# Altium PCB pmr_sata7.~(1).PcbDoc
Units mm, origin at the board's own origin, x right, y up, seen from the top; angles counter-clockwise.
Board outline 160 x 99.92 mm, 2 copper layers (Top Layer, Bottom Layer); 11 components, 38 nets, 173 pads, 16 vias.
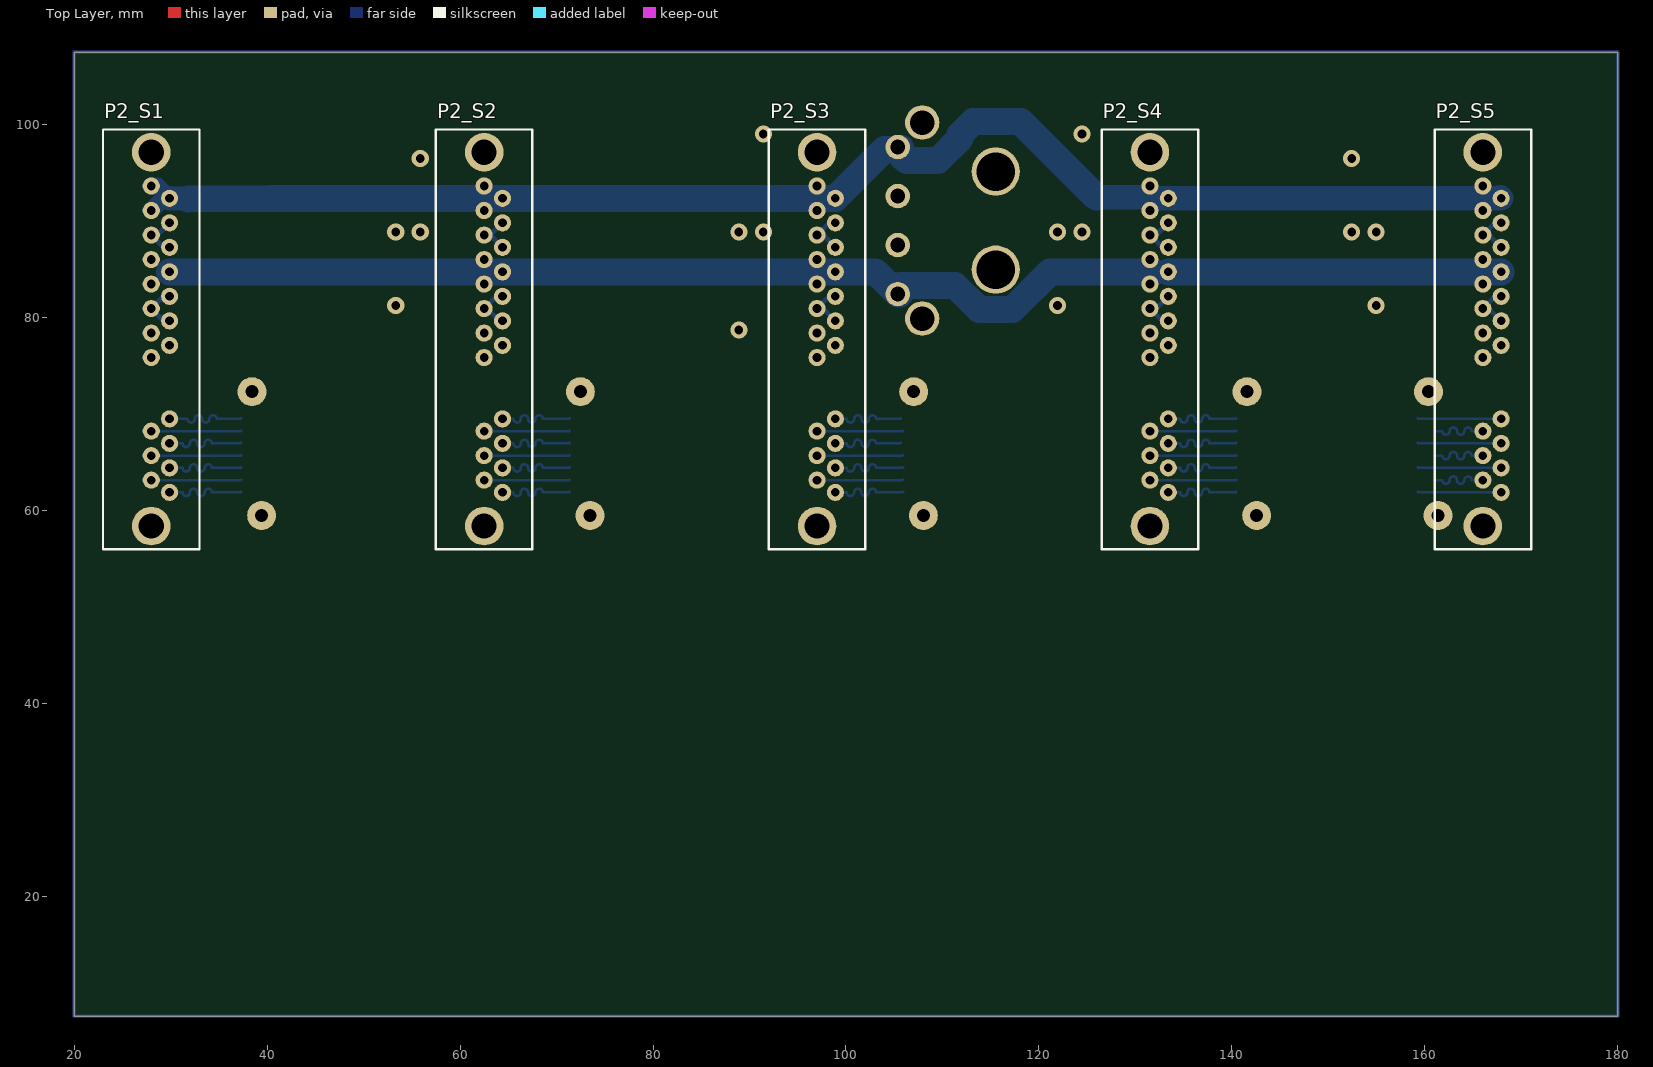
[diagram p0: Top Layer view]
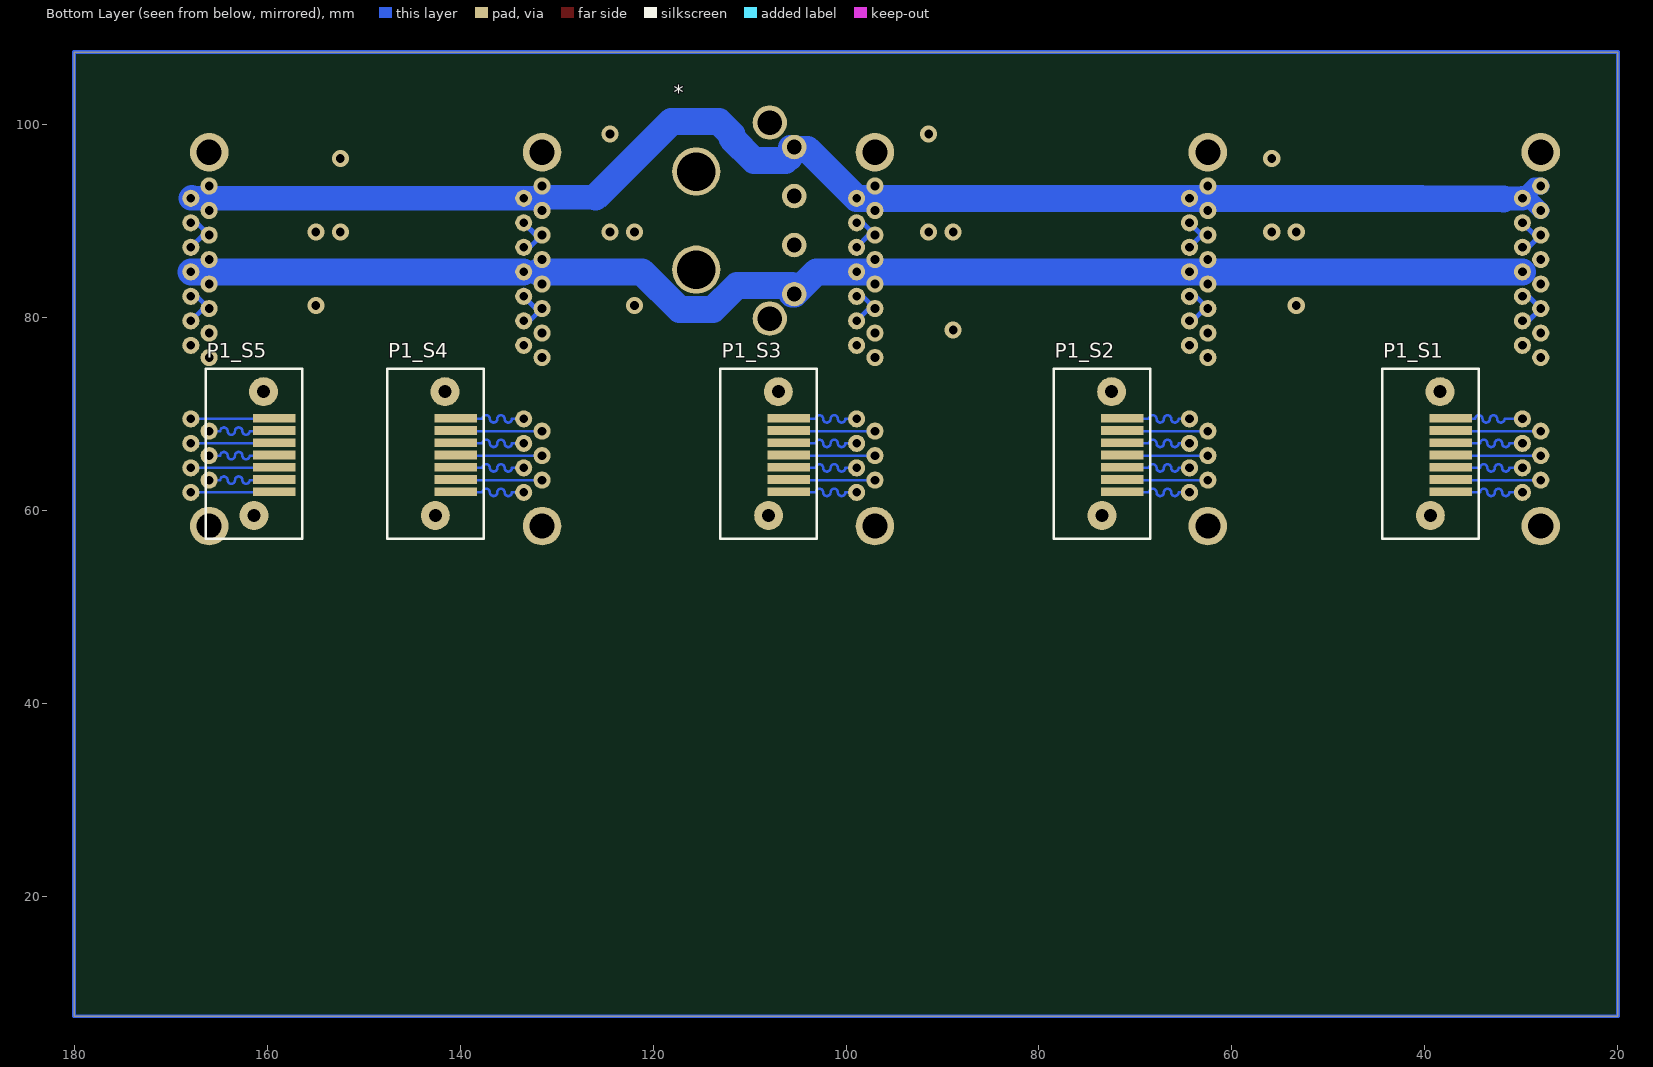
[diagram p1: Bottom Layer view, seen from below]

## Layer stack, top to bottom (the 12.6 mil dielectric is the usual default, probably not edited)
Top Solder: solder mask 0.0102, Solder Resist, Dk 3.5
Top Layer: signal copper 0.0356
Dielectric1: dielectric 0.32, FR-4, Dk 4.8
Bottom Layer: signal copper 0.0356
Bottom Solder: solder mask 0.0102, Solder Resist, Dk 3.5

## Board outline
20,7.62 20,107.544 180,107.544 180,7.62

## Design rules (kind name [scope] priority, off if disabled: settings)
Clearance [All] p1: gap=0.254
DiffPairsRouting [All] p1: maxlimit=0.254 minlimit=0.254 mostfreqgap=0.254 toplayer_minwidth=0.254 toplayer_maxwidth=0.381 toplayer_prefwidth=0.381 bottomlayer_minwidth=0.254 bottomlayer_maxwidth=0.381 bottomlayer_prefwidth=0.381 maxuncoupledlength=12.7
PolygonConnect [All] p1: connectstyle=Relief reliefconductorwidth=0.254 reliefentries=4 polygonreliefangle="90 Angle" airgapwidth=0.254
RoomDefinition top_level_sheet [InComponentClass('top_level_sheet')] p1 off: confinementstyle=ConfineIn formatcopy=TRUE lockcomponents=FALSE outline 180,10 197.5,10 197.5,37.5 180,37.5
RoomDefinition S5 [InComponentClass('S5')] p2 off: confinementstyle=ConfineIn formatcopy=TRUE lockcomponents=FALSE outline 29,122 53,122 53,170 29,170
RoomDefinition S3 [InComponentClass('S3')] p3 off: confinementstyle=ConfineIn formatcopy=TRUE lockcomponents=FALSE outline 76,114.83 100,114.83 100,162.83 76,162.83
RoomDefinition S2 [InComponentClass('S2')] p4 off: confinementstyle=ConfineIn formatcopy=TRUE lockcomponents=FALSE outline 108,115 132,115 132,163 108,163
RoomDefinition S1 [InComponentClass('S1')] p5 off: confinementstyle=ConfineIn formatcopy=TRUE lockcomponents=FALSE outline 127,116 151,116 151,164 127,164
RoomDefinition S4 [InComponentClass('S4')] p6 off: confinementstyle=ConfineIn formatcopy=TRUE lockcomponents=FALSE outline 192.278,29.464 184.912,29.464 184.912,40.386 192.278,40.386
RoutingVias [All] p1: holewidth=0.711 width=1.27 viastyle="Through Hole" minholewidth=0.711 minwidth=1.27 maxholewidth=0.711 maxwidth=1.27
SilkToSolderMaskClearance SilkscreenOverComponentPads [IsPad] p1: minsilkscreentomaskgap=0.254 clearancetoexposedcopper=TRUE
SolderMaskExpansion [All] p1: expansion=0.102
Width [All] p1: maxlimit=12.7 minlimit=0.254 preferedwidth=0.254
28 further rules are at their usual default settings.

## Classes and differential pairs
component class S1: P1_S1 P2_S1
component class S2: P1_S2 P2_S2
component class S3: P1_S3 P2_S3
component class S4: P1_S4 P2_S4
component class S5: P1_S5 P2_S5
channel class pmr_sata_single: S1 S2 S3 S4 S5
differential pair PAIR1_S1: +PAIR1_S1_P -PAIR1_S1_N
differential pair PAIR1_S2: +PAIR1_S2_P -PAIR1_S2_N
differential pair PAIR1_S3: +PAIR1_S3_P -PAIR1_S3_N
differential pair PAIR1_S4: +PAIR1_S4_P -PAIR1_S4_N
differential pair PAIR1_S5: +PAIR1_S5_P -PAIR1_S5_N
differential pair PAIR2_S1: +PAIR2_S1_P -PAIR2_S1_N
differential pair PAIR2_S2: +PAIR2_S2_P -PAIR2_S2_N
differential pair PAIR2_S3: +PAIR2_S3_P -PAIR2_S3_N
differential pair PAIR2_S4: +PAIR2_S4_P -PAIR2_S4_N
differential pair PAIR2_S5: +PAIR2_S5_P -PAIR2_S5_N

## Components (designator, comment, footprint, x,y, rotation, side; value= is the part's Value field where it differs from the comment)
* "PC_PWR_MOLEX" PC_PWR_MOLEX 115.52,90.08 r90 bottom
P1_S1 "SATA lille" "PMR_SATA -LILLE NY" 39.438,59.516 r270 bottom (schematic designator P1)
P1_S2 "SATA lille" "PMR_SATA -LILLE NY" 73.474,59.516 r270 bottom (schematic designator P1)
P1_S3 "SATA lille" "PMR_SATA -LILLE NY" 108.018,59.516 r270 bottom (schematic designator P1)
P1_S4 "SATA lille" "PMR_SATA -LILLE NY" 142.562,59.516 r270 bottom (schematic designator P1)
P1_S5 "SATA lille" "PMR_SATA -LILLE NY" 161.358,59.516 r270 bottom (schematic designator P1)
P2_S1 "SATA STOR" pmr_sata 28,58.42 r90 top (schematic designator P2)
P2_S2 "SATA STOR" pmr_sata 62.5,58.42 r90 top (schematic designator P2)
P2_S3 "SATA STOR" pmr_sata 97,58.42 r90 top (schematic designator P2)
P2_S4 "SATA STOR" pmr_sata 131.5,58.42 r90 top (schematic designator P2)
P2_S5 "SATA STOR" pmr_sata 166,58.42 r90 top (schematic designator P2)

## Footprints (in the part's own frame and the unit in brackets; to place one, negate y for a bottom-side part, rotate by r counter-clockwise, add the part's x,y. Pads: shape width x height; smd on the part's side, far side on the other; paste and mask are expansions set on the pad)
PC_PWR_MOLEX [mil]
  round 100 hole 60: 1(300,-400) 2(100,-400) 3(-100,-400) 4(-300,-400)
  round 140 hole 100: 5(400,-300) 6(-400,-300)
  round 196.85 hole 157.48: 7(-200,0) 8(200,0)
pmr_sata [mm]
  round 1.778 hole 0.9: P1(17.46,0) P2(18.73,-1.9) P3(20,0) P4(21.27,-1.9) P5(22.54,0) P6(23.81,-1.9) P7(25.08,0) P8(26.35,-1.9) P9(27.62,0) P10(28.89,-1.9) P11(30.16,0) P12(31.43,-1.9) P13(32.7,0) P14(33.97,-1.9) P15(35.24,0) S1(3.49,-1.9) S2(4.76,0) S3(6.03,-1.9) S4(7.3,0) S5(8.57,-1.9) S6(9.84,0) S7(11.11,-1.9)
  round 4 hole 2.6: S8(0,0) S8(38.74,0)
  silkscreen extent -2.4,-5 41.1,5
"PMR_SATA -LILLE NY" [mm]
  rect 0.9x4.4 smd: S1(-2.46,2.1) S2(-3.73,2.1) S3(-5,2.1) S4(-6.27,2.1) S5(-7.54,2.1) S6(-8.81,2.1) S7(-10.08,2.1)
  round 3 hole 1.35: S8(-12.83,1) S8(0,0)
  silkscreen extent -15.2,-5 2.4,5

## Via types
v1: diameter 1.778, hole 0.9, Top Layer to Bottom Layer, 16 vias

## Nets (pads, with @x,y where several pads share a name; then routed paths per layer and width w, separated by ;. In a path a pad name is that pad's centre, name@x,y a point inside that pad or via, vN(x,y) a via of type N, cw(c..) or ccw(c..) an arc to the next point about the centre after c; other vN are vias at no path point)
5V: *.4 P2_S1.P7 P2_S1.P8 P2_S1.P9 P2_S2.P7 P2_S2.P8 P2_S2.P9 P2_S3.P7 P2_S3.P8 P2_S3.P9 P2_S4.P7 P2_S4.P8 P2_S4.P9 P2_S5.P7 P2_S5.P8 P2_S5.P9 | length 141
  Bottom Layer w2.794: P2_S1.P8 P2_S2.P8 P2_S3.P8 103.05,84.77 *.4 105.591,82.46 105.591,83.349 111.301,83.349 113.801,80.849 117.239,80.849 121.16,84.77 131.92,84.77 ; P2_S4.P8 P2_S5.P8
12V: *.1 P2_S1.P13 P2_S1.P14 P2_S1.P15 P2_S2.P13 P2_S2.P14 P2_S2.P15 P2_S3.P13 P2_S3.P14 P2_S3.P15 P2_S4.P13 P2_S4.P14 P2_S4.P15 P2_S5.P13 P2_S5.P14 P2_S5.P15 | length 150.8
  Bottom Layer w1.778: P2_S1.P13 P2_S1.P14@29.27,92.39 ; P2_S1.P15 28.63,93.66 P2_S1.P14
  Bottom Layer w2.54: P2_S1.P14 31.877,92.329 ; *.1@105.116,97.456 *.1 105.77,97.7 *.1@105.77,96.52 ; 125.94,92.5 131.92,92.5 132.03,92.39 P2_S4.P14 P2_S5.P14 P2_S5.P14@167.79,92.5
  Bottom Layer w2.794: 31.877,92.329 40.386,92.373 56.896,92.373 56.913,92.39 P2_S2.P14 65.452,92.39 65.469,92.373 80.01,92.373 80.027,92.39 P2_S3.P14 103.966,97.456 *.1@105.116,97.456 ; 106.052,96.52 106.269,96.303 109.531,96.303 111.837,98.609 111.837,99.01 113.157,100.33 118.11,100.33 125.94,92.5
GND: P2_S1.P4 P2_S1.P5 P2_S1.P6 P2_S1.P10 P2_S1.P11 P2_S1.P12 P2_S2.P4 P2_S2.P5 P2_S2.P6 P2_S2.P10 P2_S2.P11 P2_S2.P12 P2_S3.P4 P2_S3.P5 P2_S3.P6 P2_S3.P10 P2_S3.P11 P2_S3.P12 P2_S4.P4 P2_S4.P5 P2_S4.P6 P2_S4.P10 P2_S4.P11 P2_S4.P12 P2_S5.P4 P2_S5.P5 P2_S5.P6 P2_S5.P10 P2_S5.P11 P2_S5.P12 | length 49.2
  Bottom Layer w0.508: P2_S1.P4 29.27,79.69 P2_S1.P5 29.27,82.23 P2_S1.P6 ; P2_S1.P10 29.27,87.31 P2_S1.P11 28.63,88.58 P2_S1.P12 ; P2_S2.P11 P2_S2.P11@63.13,88.58 ; P2_S2.P4 64.074,79.69 62.804,80.96 P2_S2.P5 63.77,82.23 P2_S2.P6 ; P2_S2.P10@64.4,86.675 P2_S2.P10 P2_S2.P11@63.13,88.58 ; P2_S2.P12 P2_S2.P11@63.13,88.58 ; P2_S3.P4 97.63,80.96 P2_S3.P5 98.27,82.23 P2_S3.P6 ; P2_S3.P10 97.63,88.58 P2_S3.P11 98.27,89.85 P2_S3.P12 ; P2_S4.P4 132.77,79.69 P2_S4.P5 132.13,80.96 P2_S4.P6 P2_S4.P6@133.4,82.865 ; P2_S4.P10 132.77,87.31 P2_S4.P11 132.13,88.58 P2_S4.P12 ; P2_S5.P4 166.63,80.96 P2_S5.P5 167.27,82.23 P2_S5.P6 ; P2_S5.P10 166.63,88.58 P2_S5.P11 167.27,89.85 P2_S5.P12
  other v1: 88.9,78.74 53.34,81.28 121.92,81.28 154.94,81.28 53.34,88.9 55.88,88.9 88.9,88.9 91.44,88.9 121.92,88.9 124.46,88.9 152.4,88.9 154.94,88.9 55.88,96.52 152.4,96.52 91.44,99.06 124.46,99.06
NetP1_S1_S1: P1_S1.S1 P2_S1.S1 | length 8.6
  Bottom Layer w0.254: P2_S1.S1@30.48,61.91 31.242,61.91 ccw(c31.623,61.91) 32.004,61.91 cw(c32.385,61.91) 32.766,61.91 ccw(c33.147,61.91) 33.528,61.91 cw(c33.909,61.91) 34.29,61.91 37.272,61.91 P1_S1.S1
NetP1_S1_S4: P1_S1.S4 P2_S1.S4 | length 9.4
  Bottom Layer w0.254: P2_S1.S4 37.272,65.72 P1_S1.S4
NetP1_S1_S7: P1_S1.S7 P2_S1.S7 | length 9.2
  Bottom Layer w0.254: P2_S1.S7 30.988,69.53 31.75,69.53 ccw(c32.131,69.53) 32.512,69.53 cw(c32.893,69.53) 33.274,69.53 ccw(c33.655,69.53) 34.036,69.53 cw(c34.417,69.53) 34.798,69.53 35.018,69.53 37.272,69.53 P1_S1.S7
NetP1_S2_S1: P1_S2.S1 P2_S2.S1 | length 8.4
  Bottom Layer w0.254: P2_S2.S1@64.77,61.91 65.532,61.91 ccw(c65.913,61.91) 66.294,61.91 cw(c66.675,61.91) 67.056,61.91 ccw(c67.437,61.91) 67.818,61.91 cw(c68.199,61.91) 68.58,61.91 71.308,61.91 P1_S2.S1
NetP1_S2_S4: P1_S2.S4 P2_S2.S4 | length 8.9
  Bottom Layer w0.254: P2_S2.S4 71.308,65.72 P1_S2.S4
NetP1_S2_S7: P1_S2.S7 P2_S2.S7 | length 8.4
  Bottom Layer w0.254: P2_S2.S7@64.77,69.53 65.532,69.53 ccw(c65.913,69.53) 66.294,69.53 cw(c66.675,69.53) 67.056,69.53 ccw(c67.437,69.53) 67.818,69.53 cw(c68.199,69.53) 68.58,69.53 71.308,69.53 P1_S2.S7
NetP1_S3_S1: P1_S3.S1 P2_S3.S1 | length 8.4
  Bottom Layer w0.254: P2_S3.S1@99.314,61.91 100.076,61.91 ccw(c100.457,61.91) 100.838,61.91 cw(c101.219,61.91) 101.6,61.91 ccw(c101.981,61.91) 102.362,61.91 cw(c102.743,61.91) 103.124,61.91 105.852,61.91 P1_S3.S1
NetP1_S3_S4: P1_S3.S4 P2_S3.S4 | length 8.9
  Bottom Layer w0.254: P2_S3.S4 105.852,65.72 P1_S3.S4
NetP1_S3_S7: P1_S3.S7 P2_S3.S7 | length 8.1
  Bottom Layer w0.254: P2_S3.S7@99.314,69.53 100.076,69.53 ccw(c100.457,69.53) 100.838,69.53 cw(c101.219,69.53) 101.6,69.53 ccw(c101.981,69.53) 102.362,69.53 cw(c102.743,69.53) 103.124,69.53 105.598,69.53 P1_S3.S7@105.664,69.596
NetP1_S4_S1: P1_S4.S1 P2_S4.S1 | length 8.4
  Bottom Layer w0.254: P2_S4.S1@133.858,61.91 134.62,61.91 ccw(c135.001,61.91) 135.382,61.91 cw(c135.763,61.91) 136.144,61.91 ccw(c136.525,61.91) 136.906,61.91 cw(c137.287,61.91) 137.668,61.91 140.396,61.91 P1_S4.S1
NetP1_S4_S4: P1_S4.S4 P2_S4.S4 | length 9
  Bottom Layer w0.254: P2_S4.S4 140.396,65.72 P1_S4.S4
NetP1_S4_S7: P1_S4.S7 P2_S4.S7 | length 8.4
  Bottom Layer w0.254: P2_S4.S7@133.858,69.53 134.62,69.53 ccw(c135.001,69.53) 135.382,69.53 cw(c135.763,69.53) 136.144,69.53 ccw(c136.525,69.53) 136.906,69.53 cw(c137.287,69.53) 137.668,69.53 140.396,69.53 P1_S4.S7
NetP1_S5_S1: P1_S5.S1 P2_S5.S1 | length 8.7
  Bottom Layer w0.254: P1_S5.S1 159.324,61.91 P2_S5.S1
NetP1_S5_S4: P1_S5.S4 P2_S5.S4 | length 5.8
  Bottom Layer w0.254: P1_S5.S4@161.036,65.72 161.798,65.72 ccw(c162.179,65.72) 162.56,65.72 cw(c162.941,65.72) 163.322,65.72 ccw(c163.703,65.72) 164.084,65.72 cw(c164.465,65.72) 164.846,65.72 165.066,65.72
NetP1_S5_S7: P1_S5.S7 P2_S5.S7 | length 8.7
  Bottom Layer w0.254: P1_S5.S7 159.324,69.53 P2_S5.S7
PAIR1_S1_N: P1_S1.S2 P2_S1.S2 | length 9.4
  Bottom Layer w0.254: P2_S1.S2 37.272,63.18 P1_S1.S2
PAIR1_S1_P: P1_S1.S3 P2_S1.S3 | length 8.6
  Bottom Layer w0.254: P2_S1.S3@30.48,64.45 31.242,64.45 ccw(c31.623,64.45) 32.004,64.45 cw(c32.385,64.45) 32.766,64.45 ccw(c33.147,64.45) 33.528,64.45 cw(c33.909,64.45) 34.29,64.45 37.272,64.45 P1_S1.S3
PAIR1_S2_N: P1_S2.S2 P2_S2.S2 | length 8.9
  Bottom Layer w0.254: P2_S2.S2 71.308,63.18 P1_S2.S2
PAIR1_S2_P: P1_S2.S3 P2_S2.S3 | length 8.4
  Bottom Layer w0.254: P2_S2.S3@64.77,64.45 65.532,64.45 ccw(c65.913,64.45) 66.294,64.45 cw(c66.675,64.45) 67.056,64.45 ccw(c67.437,64.45) 67.818,64.45 cw(c68.199,64.45) 68.58,64.45 71.308,64.45 P1_S2.S3
PAIR1_S3_N: P1_S3.S2 P2_S3.S2 | length 8.9
  Bottom Layer w0.254: P2_S3.S2 105.852,63.18 P1_S3.S2
PAIR1_S3_P: P1_S3.S3 P2_S3.S3 | length 8.4
  Bottom Layer w0.254: P2_S3.S3@99.314,64.45 100.076,64.45 ccw(c100.457,64.45) 100.838,64.45 cw(c101.219,64.45) 101.6,64.45 ccw(c101.981,64.45) 102.362,64.45 cw(c102.743,64.45) 103.124,64.45 105.852,64.45 P1_S3.S3
PAIR1_S4_N: P1_S4.S2 P2_S4.S2 | length 9.3
  Bottom Layer w0.254: P2_S4.S2 131.5,63.428 131.748,63.18 140.396,63.18 P1_S4.S2
PAIR1_S4_P: P1_S4.S3 P2_S4.S3 | length 8.4
  Bottom Layer w0.254: P2_S4.S3@133.858,64.45 134.62,64.45 ccw(c135.001,64.45) 135.382,64.45 cw(c135.763,64.45) 136.144,64.45 ccw(c136.525,64.45) 136.906,64.45 cw(c137.287,64.45) 137.668,64.45 140.396,64.45 P1_S4.S3
PAIR1_S5_N: P1_S5.S2 P2_S5.S2 | length 5.8
  Bottom Layer w0.254: P1_S5.S2@161.036,63.18 161.798,63.18 ccw(c162.179,63.18) 162.56,63.18 cw(c162.941,63.18) 163.322,63.18 ccw(c163.703,63.18) 164.084,63.18 cw(c164.465,63.18) 164.846,63.18 165.066,63.18
PAIR1_S5_P: P1_S5.S3 P2_S5.S3 | length 8.7
  Bottom Layer w0.254: P1_S5.S3 159.324,64.45 P2_S5.S3
PAIR2_S1_N: P1_S1.S5 P2_S1.S5 | length 9.2
  Bottom Layer w0.254: P2_S1.S5 31.242,66.99 ccw(c31.623,66.99) 32.004,66.99 cw(c32.385,66.99) 32.766,66.99 ccw(c33.147,66.99) 33.528,66.99 cw(c33.909,66.99) 34.29,66.99 37.272,66.99 P1_S1.S5
PAIR2_S1_P: P1_S1.S6 P2_S1.S6 | length 9.4
  Bottom Layer w0.254: P2_S1.S6 37.272,68.26 P1_S1.S6
PAIR2_S2_N: P1_S2.S5 P2_S2.S5 | length 8.4
  Bottom Layer w0.254: P2_S2.S5@64.77,66.99 65.532,66.99 ccw(c65.913,66.99) 66.294,66.99 cw(c66.675,66.99) 67.056,66.99 ccw(c67.437,66.99) 67.818,66.99 cw(c68.199,66.99) 68.58,66.99 71.308,66.99 P1_S2.S5
PAIR2_S2_P: P1_S2.S6 P2_S2.S6 | length 8.9
  Bottom Layer w0.254: P2_S2.S6 71.308,68.26 P1_S2.S6
PAIR2_S3_N: P1_S3.S5 P2_S3.S5 | length 8.1
  Bottom Layer w0.254: P2_S3.S5@99.314,66.99 100.076,66.99 ccw(c100.457,66.99) 100.838,66.99 cw(c101.219,66.99) 101.6,66.99 ccw(c101.981,66.99) 102.362,66.99 cw(c102.743,66.99) 103.124,66.99 105.598,66.99 P1_S3.S5@105.664,67.056
PAIR2_S3_P: P1_S3.S6 P2_S3.S6 | length 8.9
  Bottom Layer w0.254: P2_S3.S6 105.852,68.26 P1_S3.S6
PAIR2_S4_N: P1_S4.S5 P2_S4.S5 | length 8.4
  Bottom Layer w0.254: P2_S4.S5@133.858,66.99 134.62,66.99 ccw(c135.001,66.99) 135.382,66.99 cw(c135.763,66.99) 136.144,66.99 ccw(c136.525,66.99) 136.906,66.99 cw(c137.287,66.99) 137.668,66.99 140.396,66.99 P1_S4.S5
PAIR2_S4_P: P1_S4.S6 P2_S4.S6 | length 9
  Bottom Layer w0.254: P2_S4.S6 140.396,68.26 P1_S4.S6
PAIR2_S5_N: P1_S5.S5 P2_S5.S5 | length 8.7
  Bottom Layer w0.254: P1_S5.S5 159.324,66.99 P2_S5.S5
PAIR2_S5_P: P1_S5.S6 P2_S5.S6 | length 5.8
  Bottom Layer w0.254: P1_S5.S6@161.036,68.26 161.798,68.26 ccw(c162.179,68.26) 162.56,68.26 cw(c162.941,68.26) 163.322,68.26 ccw(c163.703,68.26) 164.084,68.26 cw(c164.465,68.26) 164.846,68.26 165.066,68.26
pads on no net: *.2 *.3 *.5 *.6 *.7 *.8 P1_S1.S8 P1_S2.S8 P1_S3.S8 P1_S4.S8 P1_S5.S8 P2_S1.P1 P2_S1.P2 P2_S1.P3 P2_S1.S8 P2_S2.P1 P2_S2.P2 P2_S2.P3 P2_S2.S8 P2_S3.P1 P2_S3.P2 P2_S3.P3 P2_S3.S8 P2_S4.P1 P2_S4.P2 P2_S4.P3 P2_S4.S8 P2_S5.P1 P2_S5.P2 P2_S5.P3 P2_S5.S8
copper on no net: | length 519.8
  Bottom Layer w0.381: 20,7.62 20,107.544 180,107.544 180,7.62 20,7.62

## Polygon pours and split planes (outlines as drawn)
GND on Bottom Layer "BOT GND" (solid, shelved, pour order 0): 20,7.62 20,107.544 180,107.544 180,7.62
